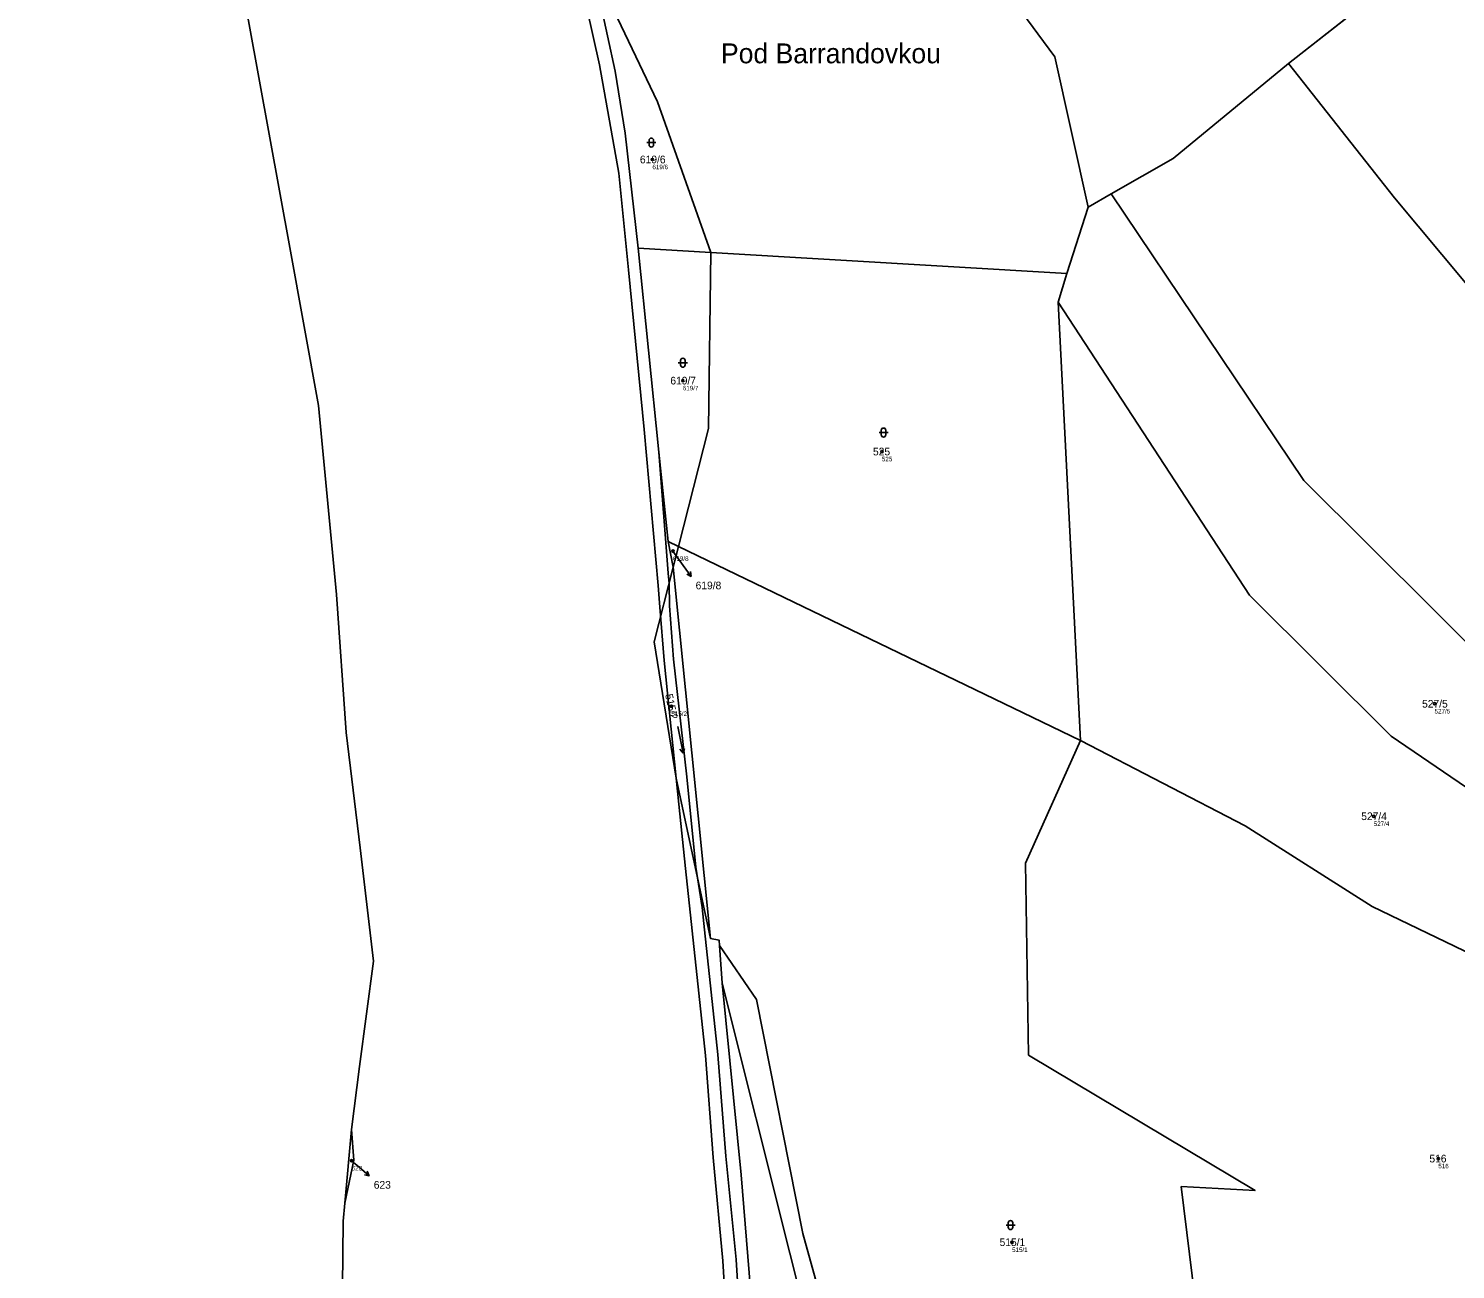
# Model space of a CAD drawing. Extents: x -766177 to -763254, y -1057727 to -1053915.
# Drawn here: x -765798.6 to -765482.3, y -1055995 to -1055720 of the extents above; entities that cross this region are included whole.
import ezdxf

# ---------------------------------------------------------------- set-up
doc = ezdxf.new("R2010")
doc.units = 0
for name, color, linetype in [('Vrstva 1', 7, 'Continuous'), ('Vrstva 13', 7, 'Continuous'), ('Vrstva 2', 7, 'Continuous'), ('Vrstva 3', 7, 'Continuous'), ('Vrstva 50', 7, 'Continuous'), ('Vrstva 51', 7, 'Continuous'), ('Vrstva 53', 7, 'Continuous'), ('Vrstva 7', 7, 'Continuous')]:
    doc.layers.add(name, color=color, linetype=linetype)

msp = doc.modelspace()

# ---------------------------------------------------------------- linework, layer by layer
at = {"layer": 'Vrstva 1'}
for p, q in [((-765519.35, -1055727.69), (-765471.72, -1055690.37)), ((-765563.73, -1055759.58), (-765558.59, -1055756.64)), ((-765568.42, -1055774.3), (-765563.73, -1055759.58)), ((-765663.43, -1055768.66), (-765647.32, -1055769.62)), ((-765568.42, -1055774.3), (-765647.32, -1055769.62)), ((-765570.37, -1055780.59), (-765568.42, -1055774.3)), ((-765565.41, -1055877.76), (-765570.37, -1055780.59)), ((-765655.71, -1055839.38), (-765656.81, -1055833.66)), ((-765656.81, -1055833.66), (-765654.53, -1055834.76)), ((-765654.53, -1055834.76), (-765655.71, -1055839.38)), ((-765565.41, -1055877.76), (-765654.53, -1055834.76)), ((-765655.71, -1055839.38), (-765647.38, -1055921.67)), ((-765645.42, -1055923.21), (-765644.86, -1055931.59)), ((-765727, -1055964.04), (-765728.43, -1055980.3))]:
    msp.add_line(p, q, dxfattribs=at)
for points in [[(-765563.73, -1055759.58), (-765571.09, -1055726.24), (-765589.51, -1055701.27), (-765620.24, -1055644.91), (-765634.62, -1055596.87), (-765638.61, -1055559.47)], [(-765798.55, -1055615.06), (-765751.96, -1055706.4), (-765740.65, -1055768.53), (-765734.28, -1055803.55), (-765730.3, -1055845.45), (-765728.18, -1055876), (-765725.07, -1055901.58), (-765722.12, -1055926.68)], [(-765663.43, -1055768.66), (-765666.29, -1055743.13), (-765668.56, -1055729.43), (-765673.61, -1055705.85)], [(-765673.61, -1055705.85), (-765659.19, -1055736.18), (-765647.32, -1055769.62)], [(-765558.59, -1055756.64), (-765544.89, -1055748.79), (-765519.35, -1055727.69)], [(-765519.35, -1055727.69), (-765495.84, -1055757.52), (-765474.85, -1055782.63), (-765439.15, -1055819.54)], [(-765558.59, -1055756.64), (-765515.89, -1055820.16), (-765458.01, -1055877.76), (-765390.75, -1055905.5)], [(-765656.81, -1055833.66), (-765658.89, -1055813.84), (-765663.43, -1055768.66)], [(-765647.32, -1055769.62), (-765647.85, -1055808.61), (-765654.53, -1055834.76)], [(-765390.71, -1055936.08), (-765424.32, -1055922.1), (-765468.24, -1055896.12), (-765496.53, -1055876.8), (-765527.97, -1055845.59), (-765570.37, -1055780.59)], [(-765655.71, -1055839.38), (-765659.92, -1055855.89), (-765655.05, -1055886.11), (-765647.38, -1055921.67)], [(-765393.26, -1056031.51), (-765411.71, -1056027.54), (-765438.99, -1056033.2), (-765475.45, -1056032.58), (-765539.39, -1056006.66), (-765543.08, -1055976.66), (-765526.71, -1055977.54), (-765576.93, -1055947.5), (-765577.6, -1055904.96), (-765565.41, -1055877.76)], [(-765389.18, -1055961), (-765436.46, -1055942.74), (-765472.22, -1055928.35), (-765500.8, -1055914.61), (-765528.9, -1055896.66), (-765565.41, -1055877.76)], [(-765647.38, -1055921.67), (-765645.5, -1055922.01), (-765645.42, -1055923.21)], [(-765593.55, -1056076.37), (-765608.54, -1056053.34), (-765626.95, -1055987.06), (-765637.2, -1055935.18), (-765645.42, -1055923.21)], [(-765722.12, -1055926.68), (-765725.18, -1055950.07), (-765727, -1055964.04)], [(-765644.86, -1055931.59), (-765614.84, -1056051.27), (-765614, -1056114.31), (-765603.2, -1056116.09)], [(-765644.86, -1055931.59), (-765640.58, -1055974.07), (-765637.37, -1056013.87), (-765635.4, -1056053.04), (-765633.16, -1056117.5)], [(-765727, -1055964.04), (-765726.45, -1055970.82), (-765728.43, -1055980.3)], [(-765728.43, -1055980.3), (-765728.79, -1055984.35), (-765728.95, -1055998.9)]]:
    msp.add_lwpolyline(points, dxfattribs=at)
at = {"layer": 'Vrstva 13'}
for points in [[(-765638.89, -1056037.87), (-765641.69, -1055992.84), (-765644.05, -1055969.95), (-765645.8, -1055947.36), (-765648.74, -1055919.76), (-765649.27, -1055914.76), (-765650.69, -1055905.87), (-765652.67, -1055885.86), (-765655.61, -1055859.72), (-765656.49, -1055847.95), (-765656.59, -1055843.01), (-765656.77, -1055840.68), (-765658.89, -1055813.84), (-765663.43, -1055768.66), (-765666.29, -1055743.13), (-765668.56, -1055729.43), (-765673.61, -1055705.85)], [(-765676.22, -1055709.12), (-765672.02, -1055728.04), (-765667.74, -1055752.06), (-765665.6, -1055773.46), (-765662.13, -1055808.86), (-765659.04, -1055843.44), (-765658.65, -1055848.2), (-765657.65, -1055860.04), (-765655.05, -1055886.11), (-765654.44, -1055891.9), (-765652.97, -1055906.13), (-765648.55, -1055947.57), (-765646.83, -1055970.2), (-765644.71, -1055993.14), (-765641.96, -1056038.12)]]:
    msp.add_lwpolyline(points, dxfattribs=at)
at = {"layer": 'Vrstva 3'}
for p, q in [((-765661.031, -1055744.761), (-765661.031, -1055745.762)), ((-765660.029, -1055745.762), (-765660.029, -1055744.761)), ((-765661.531, -1055745.261), (-765659.529, -1055745.261)), ((-765654.541, -1055794.041), (-765652.539, -1055794.041)), ((-765654.041, -1055793.541), (-765654.041, -1055794.542)), ((-765653.039, -1055794.542), (-765653.039, -1055793.541)), ((-765610.061, -1055809.511), (-765608.059, -1055809.511)), ((-765609.561, -1055809.011), (-765609.561, -1055810.012)), ((-765608.559, -1055810.012), (-765608.559, -1055809.011)), ((-765654.648, -1055874.684), (-765653.503, -1055880.573)), ((-765653.503, -1055880.573), (-765654.181, -1055879.71)), ((-765653.503, -1055880.573), (-765653.197, -1055879.518)), ((-765581.911, -1055985.181), (-765579.909, -1055985.181)), ((-765581.411, -1055984.681), (-765581.411, -1055985.682)), ((-765580.409, -1055985.682), (-765580.409, -1055984.681))]:
    msp.add_line(p, q, dxfattribs=at)
for centre, start, end in [((-765660.53, -1055744.7609), 0, 180), ((-765660.53, -1055745.7609), 180, 359.9878861), ((-765653.54, -1055793.5409), 0, 180), ((-765653.54, -1055794.5409), 180, 359.9878861), ((-765609.06, -1055809.0109), 0, 180), ((-765609.06, -1055810.0109), 180, 359.9878861), ((-765580.91, -1055984.6809), 0, 180), ((-765580.91, -1055985.6809), 180, 359.9878861)]:
    msp.add_arc(centre, 0.5, start, end, dxfattribs=at)
at = {"layer": 'Vrstva 50'}
for centre in [(-765660.28, -1055748.98994), (-765653.54, -1055798.00994), (-765609.43, -1055813.72994), (-765655.73, -1055835.79994), (-765656.07, -1055870.17994), (-765486.94, -1055869.63994), (-765500.42, -1055894.56994), (-765726.94, -1055970.92994), (-765486.11, -1055970.44994), (-765580.57, -1055988.98994)]:
    msp.add_circle(centre, 0.25, dxfattribs=at)
at = {"layer": 'Vrstva 51'}
for points in [[(-765634.62, -1055596.87), (-765638.61, -1055559.47), (-765665.9, -1055523.35), (-765760.62, -1055508.03), (-765747.53, -1055533.41), (-765727.52, -1055576.43), (-765710.28, -1055612.04), (-765692.8, -1055649.63), (-765686.91, -1055665.07), (-765679.16, -1055685.98), (-765673.61, -1055705.85), (-765659.19, -1055736.18), (-765647.32, -1055769.62), (-765568.42, -1055774.3), (-765563.73, -1055759.58), (-765571.09, -1055726.24), (-765589.51, -1055701.27), (-765620.24, -1055644.91)], [(-765472.71, -1055689.23), (-765477.7, -1055675.59), (-765501.79, -1055634.63), (-765552.19, -1055524.76), (-765565.58, -1055531.69), (-765593.71, -1055540.58), (-765638.61, -1055559.47), (-765634.62, -1055596.87), (-765620.24, -1055644.91), (-765589.51, -1055701.27), (-765571.09, -1055726.24), (-765563.73, -1055759.58), (-765558.59, -1055756.64), (-765544.89, -1055748.79), (-765519.35, -1055727.69), (-765471.72, -1055690.37)], [(-765404.25, -1055780.54), (-765429.26, -1055744.62), (-765450.41, -1055715.1), (-765471.72, -1055690.37), (-765519.35, -1055727.69), (-765495.84, -1055757.52), (-765474.85, -1055782.63), (-765439.15, -1055819.54)], [(-765647.32, -1055769.62), (-765659.19, -1055736.18), (-765673.61, -1055705.85), (-765668.56, -1055729.43), (-765666.29, -1055743.13), (-765663.43, -1055768.66)], [(-765515.89, -1055820.16), (-765458.01, -1055877.76), (-765390.75, -1055905.5), (-765395.3, -1055858.4), (-765415.56, -1055847.37), (-765447.23, -1055828.57), (-765439.15, -1055819.54), (-765474.85, -1055782.63), (-765495.84, -1055757.52), (-765519.35, -1055727.69), (-765544.89, -1055748.79), (-765558.59, -1055756.64)], [(-765390.71, -1055936.08), (-765389.47, -1055918.75), (-765390.75, -1055905.5), (-765458.01, -1055877.76), (-765515.89, -1055820.16), (-765558.59, -1055756.64), (-765563.73, -1055759.58), (-765568.42, -1055774.3), (-765570.37, -1055780.59), (-765527.97, -1055845.59), (-765496.53, -1055876.8), (-765468.24, -1055896.12), (-765424.32, -1055922.1)], [(-765654.53, -1055834.76), (-765647.85, -1055808.61), (-765647.32, -1055769.62), (-765663.43, -1055768.66), (-765658.89, -1055813.84), (-765656.81, -1055833.66)], [(-765570.37, -1055780.59), (-765568.42, -1055774.3), (-765647.32, -1055769.62), (-765647.85, -1055808.61), (-765654.53, -1055834.76), (-765565.41, -1055877.76)], [(-765496.53, -1055876.8), (-765527.97, -1055845.59), (-765570.37, -1055780.59), (-765565.41, -1055877.76), (-765528.9, -1055896.66), (-765500.8, -1055914.61), (-765472.22, -1055928.35), (-765436.46, -1055942.74), (-765389.18, -1055961), (-765391.4, -1055945.79), (-765390.71, -1055936.08), (-765424.32, -1055922.1), (-765468.24, -1055896.12)], [(-765655.71, -1055839.38), (-765654.53, -1055834.76), (-765656.81, -1055833.66)], [(-765411.71, -1056027.54), (-765438.99, -1056033.2), (-765475.45, -1056032.58), (-765539.39, -1056006.66), (-765543.08, -1055976.66), (-765526.71, -1055977.54), (-765576.93, -1055947.5), (-765577.6, -1055904.96), (-765565.41, -1055877.76), (-765654.53, -1055834.76), (-765655.71, -1055839.38), (-765647.38, -1055921.67), (-765645.5, -1055922.01), (-765645.42, -1055923.21), (-765637.2, -1055935.18), (-765626.95, -1055987.06), (-765608.54, -1056053.34), (-765593.55, -1056076.37), (-765387.38, -1056062.54), (-765393.26, -1056031.51)], [(-765659.92, -1055855.89), (-765655.05, -1055886.11), (-765647.38, -1055921.67), (-765655.71, -1055839.38)], [(-765472.22, -1055928.35), (-765500.8, -1055914.61), (-765528.9, -1055896.66), (-765565.41, -1055877.76), (-765577.6, -1055904.96), (-765576.93, -1055947.5), (-765526.71, -1055977.54), (-765543.08, -1055976.66), (-765539.39, -1056006.66), (-765475.45, -1056032.58), (-765438.99, -1056033.2), (-765411.71, -1056027.54), (-765393.26, -1056031.51), (-765388.87, -1055998.98), (-765385.72, -1055984.71), (-765389.18, -1055961), (-765436.46, -1055942.74)], [(-765637.2, -1055935.18), (-765645.42, -1055923.21), (-765644.86, -1055931.59), (-765614.84, -1056051.27), (-765614, -1056114.31), (-765603.2, -1056116.09), (-765595.04, -1056115.54), (-765593.55, -1056076.37), (-765608.54, -1056053.34), (-765626.95, -1055987.06)], [(-765640.58, -1055974.07), (-765637.37, -1056013.87), (-765635.4, -1056053.04), (-765633.16, -1056117.5), (-765621.18, -1056116.94), (-765603.2, -1056116.09), (-765614, -1056114.31), (-765614.84, -1056051.27), (-765644.86, -1055931.59)], [(-765728.43, -1055980.3), (-765726.45, -1055970.82), (-765727, -1055964.04)]]:
    msp.add_lwpolyline(points, close=True, dxfattribs=at)
for points in [[(-765751.96, -1055706.4), (-765740.65, -1055768.53), (-765734.28, -1055803.55), (-765730.3, -1055845.45), (-765728.18, -1055876), (-765725.07, -1055901.58), (-765722.12, -1055926.68), (-765725.18, -1055950.07), (-765727, -1055964.04), (-765726.45, -1055970.82), (-765728.43, -1055980.3), (-765728.79, -1055984.35), (-765728.95, -1055998.9), (-765702.47, -1056384.38)], [(-765645.42, -1055923.21), (-765645.5, -1055922.01), (-765647.38, -1055921.67), (-765655.05, -1055886.11), (-765659.92, -1055855.89), (-765655.71, -1055839.38), (-765656.81, -1055833.66), (-765658.89, -1055813.84), (-765663.43, -1055768.66), (-765666.29, -1055743.13), (-765668.56, -1055729.43), (-765673.61, -1055705.85)], [(-765616.86, -1056427.33), (-765624.14, -1056305.28), (-765625.47, -1056282.85), (-765626.25, -1056263.32), (-765627.11, -1056245.09), (-765628.71, -1056223.4), (-765631.05, -1056178.46), (-765632.41, -1056132.45), (-765633.16, -1056117.5), (-765635.4, -1056053.04), (-765637.37, -1056013.87), (-765640.58, -1055974.07), (-765644.86, -1055931.59), (-765645.42, -1055923.21)]]:
    msp.add_lwpolyline(points, dxfattribs=at)
at = {"layer": 'Vrstva 53'}
msp.add_lwpolyline([(-765751.96, -1055706.4), (-765740.65, -1055768.53), (-765734.28, -1055803.55), (-765730.3, -1055845.45), (-765728.18, -1055876), (-765725.07, -1055901.58), (-765722.12, -1055926.68), (-765725.18, -1055950.07), (-765727, -1055964.04), (-765728.43, -1055980.3), (-765728.79, -1055984.35), (-765728.95, -1055998.9), (-765729.1, -1056020.38), (-765729.16, -1056040.93), (-765728.73, -1056077.66), (-765726.15, -1056111.43), (-765722.95, -1056151.55), (-765715.51, -1056262.47), (-765706.37, -1056392.79)], dxfattribs=at)
at = {"layer": 'Vrstva 7'}
for p, q in [((-765655.73, -1055835.8), (-765653.45, -1055838.99)), ((-765653.45, -1055838.99), (-765651.686, -1055841.418)), ((-765651.686, -1055841.418), (-765652.68, -1055840.902)), ((-765651.686, -1055841.418), (-765651.87, -1055840.313)), ((-765726.94, -1055970.93), (-765725.31, -1055972.33)), ((-765725.31, -1055972.33), (-765723.045, -1055974.299)), ((-765723.045, -1055974.299), (-765724.129, -1055974.02)), ((-765723.045, -1055974.299), (-765723.472, -1055973.264))]:
    msp.add_line(p, q, dxfattribs=at)

# ---------------------------------------------------------------- texts
at = {"layer": 'Vrstva 2'}
for s, p in [('619/6', (-765663.053, -1055749.84)), ('619/7', (-765656.313, -1055798.86)), ('525', (-765611.404, -1055814.58)), ('619/8', (-765650.71, -1055844.263)), ('527/5', (-765489.713, -1055870.49)), ('527/4', (-765503.193, -1055895.42)), ('516', (-765488.084, -1055971.3)), ('623', (-765722.04, -1055977.123)), ('515/1', (-765583.343, -1055989.84))]:
    msp.add_text(s, height=1.699998, dxfattribs=at).set_placement(p)
msp.add_text('515/2', height=1.699998, rotation=282, dxfattribs=at).set_placement((-765657.478, -1055867.643))
at = {"layer": 'Vrstva 50'}
for s, p in [('619/6', (-765660.28, -1055751.146)), ('619/7', (-765653.54, -1055800.166)), ('525', (-765609.43, -1055815.886)), ('619/8', (-765655.73, -1055837.956)), ('515/2', (-765656.07, -1055872.336)), ('527/5', (-765486.94, -1055871.796)), ('527/4', (-765500.42, -1055896.726)), ('623', (-765726.94, -1055973.086)), ('516', (-765486.11, -1055972.606)), ('515/1', (-765580.57, -1055991.146))]:
    msp.add_text(s, height=0.999996, dxfattribs=at).set_placement(p)
at = {"layer": 'Vrstva 7'}
msp.add_text('Pod Barrandovkou', height=4.399998, dxfattribs=at).set_placement((-765645.091, -1055727.669))

doc.saveas('drawing.dxf')
